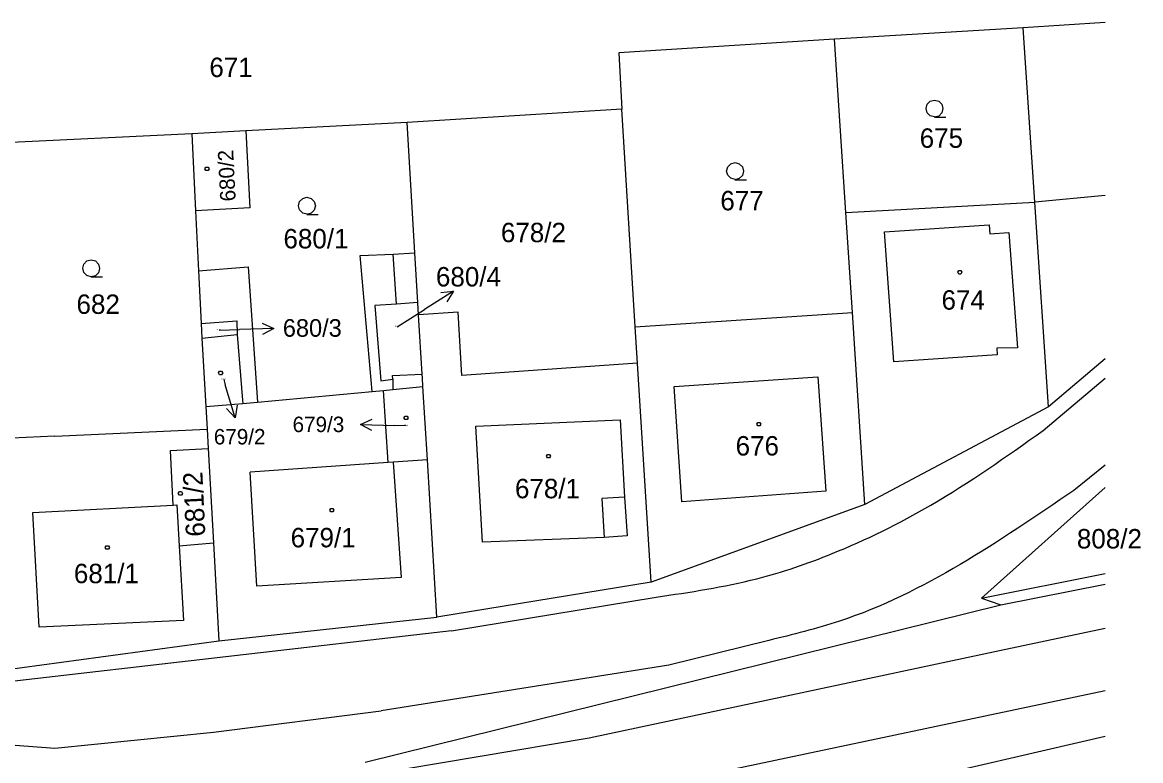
# Model space of a CAD drawing. Extents: x -621797 to -620972, y -1175539 to -1174697.
# Drawn here: x -621071.9 to -620974, y -1175130.5 to -1175066 of the extents above; entities that cross this region are included whole.
import ezdxf

# ---------------------------------------------------------------- set-up
doc = ezdxf.new("R2010")
doc.units = 0
for name, color, linetype in [('INZ mimo EON - nadz', 7, 'Continuous'), ('Rozvod plynu EON', 7, 'Continuous'), ('SDEL EON', 7, 'Continuous'), ('SDEL EON - popis', 7, 'Continuous'), ('Silnoproud EON', 7, 'Continuous'), ('Silnoproud EON - popis', 7, 'Continuous')]:
    doc.layers.add(name, color=color, linetype=linetype)

msp = doc.modelspace()

# ---------------------------------------------------------------- linework, layer by layer
at = {"layer": 'INZ mimo EON - nadz'}
for p, q in [((-621034.149, -1175089.46), (-621036.68, -1175091.07)), ((-621039.07, -1175092.59), (-621036.68, -1175091.07)), ((-621054.64, -1175092.87), (-621052.86, -1175092.82)), ((-621049.861, -1175092.731), (-621052.86, -1175092.82)), ((-621054.24, -1175097.2), (-621054.1, -1175097.67)), ((-621053.244, -1175100.545), (-621054.1, -1175097.67)), ((-621042.278, -1175101.123), (-621039.28, -1175101.23)), ((-621038.29, -1175101.26), (-621039.28, -1175101.23))]:
    msp.add_line(p, q, dxfattribs=at)
for points in [[(-621035.261, -1175089.575), (-621034.149, -1175089.46), (-621034.724, -1175090.418)], [(-621050.876, -1175092.261), (-621049.861, -1175092.731), (-621050.846, -1175093.261)], [(-621053.05, -1175099.444), (-621053.244, -1175100.545), (-621054.008, -1175099.73)], [(-621041.297, -1175101.658), (-621042.278, -1175101.123), (-621041.261, -1175100.659)]]:
    msp.add_lwpolyline(points, dxfattribs=at)
at = {"layer": 'Rozvod plynu EON'}
for points in [[(-621055.61, -1175078.61), (-621055.52, -1175078.76), (-621055.61, -1175078.91), (-621055.79, -1175078.91), (-621055.88, -1175078.76), (-621055.79, -1175078.61)], [(-620989.77, -1175087.67), (-620989.68, -1175087.82), (-620989.77, -1175087.97), (-620989.95, -1175087.97), (-620990.04, -1175087.82), (-620989.95, -1175087.67)], [(-621054.42, -1175096.48), (-621054.33, -1175096.63), (-621054.42, -1175096.78), (-621054.6, -1175096.78), (-621054.69, -1175096.63), (-621054.6, -1175096.48)], [(-621038.2, -1175100.4), (-621038.11, -1175100.55), (-621038.2, -1175100.7), (-621038.38, -1175100.7), (-621038.47, -1175100.55), (-621038.38, -1175100.4)], [(-621007.34, -1175100.96), (-621007.25, -1175101.11), (-621007.34, -1175101.26), (-621007.52, -1175101.26), (-621007.61, -1175101.11), (-621007.52, -1175100.96)], [(-621025.75, -1175103.76), (-621025.66, -1175103.91), (-621025.75, -1175104.06), (-621025.93, -1175104.06), (-621026.02, -1175103.91), (-621025.93, -1175103.76)], [(-621057.94, -1175107.01), (-621057.85, -1175107.16), (-621057.94, -1175107.31), (-621058.12, -1175107.31), (-621058.21, -1175107.16), (-621058.12, -1175107.01)], [(-621044.69, -1175108.49), (-621044.6, -1175108.64), (-621044.69, -1175108.79), (-621044.87, -1175108.79), (-621044.96, -1175108.64), (-621044.87, -1175108.49)], [(-621064.33, -1175111.74), (-621064.24, -1175111.89), (-621064.33, -1175112.04), (-621064.51, -1175112.04), (-621064.6, -1175111.89), (-621064.51, -1175111.74)]]:
    msp.add_lwpolyline(points, close=True, dxfattribs=at)
at = {"layer": 'SDEL EON'}
for points in [[(-620992.06, -1175074.23), (-620992.44, -1175074.13), (-620992.71, -1175073.86), (-620992.81, -1175073.49), (-620992.71, -1175073.12), (-620992.44, -1175072.85), (-620992.07, -1175072.75), (-620991.7, -1175072.85), (-620991.43, -1175073.12), (-620991.33, -1175073.5), (-620991.43, -1175073.88), (-620991.7, -1175074.15), (-620992.08, -1175074.25), (-620991.08, -1175074.25)], [(-621009.5, -1175079.7), (-621009.88, -1175079.6), (-621010.15, -1175079.33), (-621010.25, -1175078.96), (-621010.15, -1175078.59), (-621009.88, -1175078.32), (-621009.51, -1175078.22), (-621009.14, -1175078.32), (-621008.87, -1175078.59), (-621008.77, -1175078.97), (-621008.87, -1175079.35), (-621009.14, -1175079.62), (-621009.52, -1175079.72), (-621008.52, -1175079.72)], [(-621046.95, -1175082.74), (-621047.33, -1175082.64), (-621047.6, -1175082.37), (-621047.7, -1175082), (-621047.6, -1175081.63), (-621047.33, -1175081.36), (-621046.96, -1175081.26), (-621046.59, -1175081.36), (-621046.32, -1175081.63), (-621046.22, -1175082.01), (-621046.32, -1175082.39), (-621046.59, -1175082.66), (-621046.97, -1175082.76), (-621045.97, -1175082.76)], [(-621065.82, -1175088.21), (-621066.2, -1175088.11), (-621066.47, -1175087.84), (-621066.57, -1175087.47), (-621066.47, -1175087.1), (-621066.2, -1175086.83), (-621065.83, -1175086.73), (-621065.46, -1175086.83), (-621065.19, -1175087.1), (-621065.09, -1175087.48), (-621065.19, -1175087.86), (-621065.46, -1175088.13), (-621065.84, -1175088.23), (-621064.84, -1175088.23)]]:
    msp.add_lwpolyline(points, dxfattribs=at)
at = {"layer": 'SDEL EON - popis'}
for p, q in [((-620996.43, -1175084.28), (-620987.28, -1175083.68)), ((-620987.28, -1175083.68), (-620987.23, -1175084.46)), ((-620995.64, -1175095.64), (-620996.43, -1175084.28)), ((-620987.23, -1175084.46), (-620985.56, -1175084.34)), ((-620985.56, -1175084.34), (-620984.82, -1175094.44)), ((-621039.14, -1175090.6), (-621039.43, -1175086.24)), ((-621039.14, -1175090.6), (-621041.03, -1175090.73)), ((-621041.03, -1175090.73), (-621040.5, -1175097.32)), ((-621037.25, -1175090.47), (-621039.14, -1175090.6)), ((-621056.21, -1175092.29), (-621053.08, -1175092.08)), ((-621053.08, -1175092.08), (-621053.05, -1175093.27)), ((-620984.82, -1175094.44), (-620986.62, -1175094.46)), ((-620986.62, -1175094.46), (-620986.59, -1175095.03)), ((-620986.59, -1175095.03), (-620995.64, -1175095.64)), ((-621039.47, -1175096.84), (-621036.88, -1175096.73)), ((-621039.46, -1175097.16), (-621039.47, -1175096.84)), ((-621040.5, -1175097.32), (-621039.46, -1175097.16)), ((-621039.46, -1175097.16), (-621039.45, -1175098.07)), ((-621014.83, -1175097.8), (-621002.27, -1175096.97)), ((-621014.16, -1175107.89), (-621014.83, -1175097.8)), ((-621002.27, -1175096.97), (-621001.58, -1175106.96)), ((-620982.57, -1175101.67), (-620977.15, -1175097.087)), ((-621032.2, -1175101.27), (-621019.56, -1175100.73)), ((-621019.56, -1175100.73), (-621019.18, -1175107.49)), ((-621031.59, -1175111.42), (-621032.2, -1175101.27)), ((-621039.85, -1175104.47), (-621051.93, -1175105.31)), ((-621039.43, -1175104.44), (-621038.73, -1175114.53)), ((-620977.15, -1175104.689), (-620979.89, -1175106.9)), ((-621051.35, -1175115.28), (-621051.93, -1175105.31)), ((-621019.18, -1175107.49), (-621021.18, -1175107.62)), ((-621021.18, -1175107.62), (-621020.95, -1175111.02)), ((-621019.18, -1175107.49), (-621018.95, -1175110.88)), ((-621001.58, -1175106.96), (-621014.16, -1175107.89)), ((-621070.93, -1175108.82), (-621058.65, -1175108.18)), ((-621070.37, -1175118.86), (-621070.93, -1175108.82)), ((-621020.95, -1175111.02), (-621031.59, -1175111.42)), ((-621018.95, -1175110.88), (-621020.95, -1175111.02)), ((-621058.14, -1175111.75), (-621057.76, -1175118.28)), ((-621038.73, -1175114.53), (-621051.35, -1175115.28)), ((-620987.95, -1175116.33), (-620977.15, -1175114.163)), ((-621034.32, -1175119.19), (-621016.41, -1175116.24)), ((-621057.76, -1175118.28), (-621070.37, -1175118.86)), ((-621034.32, -1175119.19), (-621073.79, -1175123.74)), ((-620986.39, -1175120.92), (-620977.15, -1175118.95)), ((-621006.55, -1175120.02), (-621015.31, -1175122.2)), ((-621022.28, -1175128.54), (-620986.39, -1175120.92)), ((-621015.31, -1175122.2), (-621040.47, -1175126.18)), ((-621147.44, -1175123.51), (-621069.02, -1175129.45)), ((-620977.15, -1175124.433), (-621021.43, -1175133.77)), ((-621055.14, -1175128.06), (-621040.47, -1175126.18)), ((-621069.02, -1175129.45), (-621055.14, -1175128.06)), ((-621041.68, -1175131.8), (-621022.28, -1175128.54))]:
    msp.add_line(p, q, dxfattribs=at)
for points in [[(-621016.41, -1175116.24), (-621007.62, -1175114.63), (-621001.01, -1175112.43), (-620992.39, -1175108.19), (-620982.57, -1175101.67)], [(-620979.89, -1175106.9), (-620989.81, -1175113.37), (-621000.38, -1175118.34), (-621006.55, -1175120.02)]]:
    msp.add_spline(points, degree=3, dxfattribs=at)
at = {"layer": 'Silnoproud EON'}
for p, q in [((-620984.3, -1175066.42), (-621000.82, -1175067.43)), ((-620977.15, -1175065.956), (-620984.3, -1175066.42)), ((-620983.29, -1175081.69), (-620984.3, -1175066.42)), ((-621000.82, -1175067.43), (-621019.69, -1175068.62)), ((-620999.83, -1175082.59), (-621000.82, -1175067.43)), ((-621019.69, -1175068.62), (-621019.42, -1175073.56)), ((-621019.42, -1175073.56), (-621038.2, -1175074.72)), ((-621018.24, -1175092.6), (-621019.42, -1175073.56)), ((-621038.2, -1175074.72), (-621052.29, -1175075.45)), ((-621037.52, -1175086.11), (-621038.2, -1175074.72)), ((-621057.04, -1175075.7), (-621075.86, -1175076.61)), ((-621052.29, -1175075.45), (-621057.04, -1175075.7)), ((-621057.04, -1175075.7), (-621056.71, -1175082.43)), ((-621052.29, -1175075.45), (-621051.96, -1175082.19)), ((-620977.15, -1175081.105), (-620983.29, -1175081.69)), ((-621051.96, -1175082.19), (-621056.71, -1175082.43)), ((-620999.83, -1175082.59), (-620983.29, -1175081.69)), ((-620982.11, -1175099.59), (-620983.29, -1175081.69)), ((-621056.71, -1175082.43), (-621056.45, -1175087.68)), ((-620999.25, -1175091.35), (-620999.83, -1175082.59)), ((-621039.43, -1175086.24), (-621037.52, -1175086.11)), ((-621037.25, -1175090.47), (-621037.52, -1175086.11)), ((-621042.3, -1175086.36), (-621039.43, -1175086.24)), ((-621041.24, -1175098.24), (-621042.3, -1175086.36)), ((-621056.45, -1175087.68), (-621052.11, -1175087.35)), ((-621056.45, -1175087.68), (-621056.21, -1175092.29)), ((-621052.11, -1175087.35), (-621051.27, -1175099.19)), ((-621037.19, -1175091.53), (-621037.25, -1175090.47)), ((-621033.74, -1175091.32), (-621037.19, -1175091.53)), ((-621036.88, -1175096.73), (-621037.19, -1175091.53)), ((-621033.41, -1175096.85), (-621033.74, -1175091.32)), ((-621018.24, -1175092.6), (-620999.25, -1175091.35)), ((-620998.16, -1175108.12), (-620999.25, -1175091.35)), ((-621056.21, -1175092.29), (-621056.15, -1175093.57)), ((-621018.04, -1175095.76), (-621018.24, -1175092.6)), ((-621056.15, -1175093.57), (-621053.05, -1175093.27)), ((-621056.15, -1175093.57), (-621055.79, -1175099.56)), ((-621053.05, -1175093.27), (-621052.6, -1175099)), ((-621018.04, -1175095.76), (-621033.41, -1175096.85)), ((-621016.85, -1175114.92), (-621018.04, -1175095.76)), ((-620977.15, -1175095.391), (-620982.11, -1175099.59)), ((-621036.86, -1175097.06), (-621036.88, -1175096.73)), ((-621039.45, -1175098.07), (-621036.81, -1175097.82)), ((-621036.81, -1175097.82), (-621036.86, -1175097.06)), ((-621036.42, -1175104.24), (-621036.81, -1175097.82)), ((-621051.27, -1175099.19), (-621041.24, -1175098.24)), ((-621041.24, -1175098.24), (-621040.26, -1175098.15)), ((-621040.26, -1175098.15), (-621039.45, -1175098.07)), ((-621039.85, -1175104.47), (-621040.26, -1175098.15)), ((-621055.79, -1175099.56), (-621052.58, -1175099.31)), ((-621055.79, -1175099.56), (-621055.68, -1175101.55)), ((-621052.6, -1175099), (-621052.58, -1175099.31)), ((-621052.58, -1175099.31), (-621051.27, -1175099.19)), ((-620982.11, -1175099.59), (-620998.16, -1175108.12)), ((-621069.01, -1175102.16), (-621055.68, -1175101.55)), ((-621055.68, -1175101.55), (-621055.59, -1175103.24)), ((-621069.01, -1175102.16), (-621074.59, -1175102.41)), ((-621058.88, -1175103.42), (-621055.59, -1175103.24)), ((-621058.65, -1175108.18), (-621058.88, -1175103.42)), ((-621055.59, -1175103.24), (-621055.14, -1175111.49)), ((-621039.43, -1175104.44), (-621039.85, -1175104.47)), ((-621036.42, -1175104.24), (-621039.43, -1175104.44)), ((-621035.6, -1175117.98), (-621036.42, -1175104.24)), ((-620977.15, -1175106.649), (-620987.95, -1175116.33)), ((-621058.65, -1175108.18), (-621058.35, -1175108.16)), ((-621058.35, -1175108.16), (-621058.14, -1175111.75)), ((-620998.16, -1175108.12), (-621016.85, -1175114.92)), ((-621058.14, -1175111.75), (-621055.14, -1175111.49)), ((-621055.14, -1175111.49), (-621054.67, -1175120.05)), ((-621016.85, -1175114.92), (-621035.6, -1175117.98)), ((-620986.27, -1175116.91), (-620977.15, -1175115.117)), ((-620987.95, -1175116.33), (-620986.27, -1175116.91)), ((-621041.88, -1175130.69), (-620986.27, -1175116.91)), ((-621054.67, -1175120.05), (-621035.6, -1175117.98)), ((-621073.6, -1175122.62), (-621054.67, -1175120.05)), ((-620977.15, -1175128.429), (-620997.97, -1175133.24))]:
    msp.add_line(p, q, dxfattribs=at)

# ---------------------------------------------------------------- texts
at = {"layer": 'INZ mimo EON - nadz'}
for s, height, p in [('680/4', 1.7, (-621035.677, -1175089.06)), ('680/3', 1.54, (-621049.067, -1175093.46)), ('679/3', 1.35, (-621048.214, -1175101.8)), ('679/2', 1.35, (-621055.103, -1175102.88))]:
    msp.add_text(s, height=height, dxfattribs=at).set_placement(p)
at = {"layer": 'Silnoproud EON - popis'}
for s, height, p in [('671', 1.7, (-621055.493, -1175070.74)), ('675', 1.7, (-620993.363, -1175076.93)), ('677', 1.7, (-621010.803, -1175082.4)), ('680/1', 1.7, (-621049.013, -1175085.73)), ('678/2', 1.7, (-621029.993, -1175085.19)), ('682', 1.7, (-621067.113, -1175091.46)), ('674', 1.7, (-620991.453, -1175091.09)), ('680/3', 0.1, (-621054.85, -1175092.87)), ('680/4', 0.1, (-621039.275, -1175092.59)), ('679/2', 0.1, (-621054.444, -1175097.2)), ('679/3', 0.1, (-621038.495, -1175101.26)), ('676', 1.7, (-621009.463, -1175103.85)), ('678/1', 1.7, (-621028.762, -1175107.59)), ('679/1', 1.7, (-621048.385, -1175111.88)), ('808/2', 1.7, (-620979.613, -1175111.98)), ('681/1', 1.7, (-621067.344, -1175115.02))]:
    msp.add_text(s, height=height, dxfattribs=at).set_placement(p)
for s, height, rotation, p in [('680/2', 1.35, 92.93376, (-621053.185, -1175081.584)), ('681/2', 1.7, 92.70457, (-621055.84, -1175110.912))]:
    msp.add_text(s, height=height, rotation=rotation, dxfattribs=at).set_placement(p)

doc.saveas('drawing.dxf')
